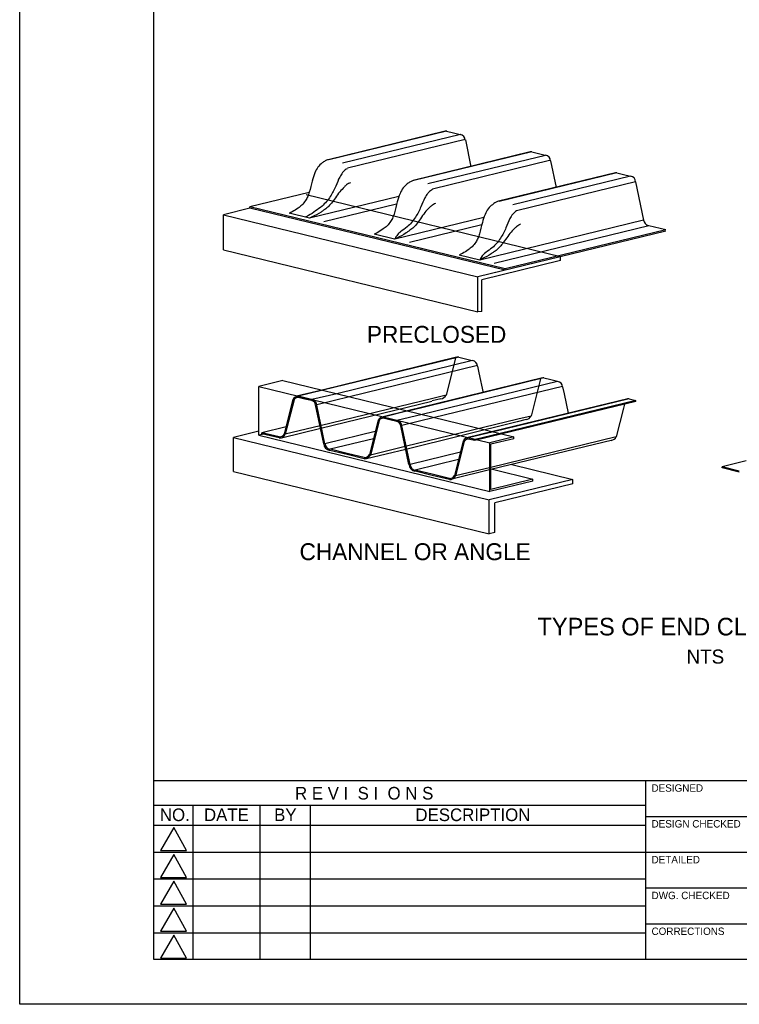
# Model space of a CAD drawing. Extents: x 0 to 34, y 0 to 23.5.
# Drawn here: x 0 to 8.04, y 0 to 11 of the extents above; entities that cross this region are included whole.
import ezdxf

# ---------------------------------------------------------------- set-up
doc = ezdxf.new("R2010")
doc.units = 0
for name, color, linetype in [('BORDER_ANNO_Cutsheet', 7, 'Continuous'), ('BRDG_ANNO_Anno-Sheet', 7, 'Continuous'), ('BRDG_ANNO_General-Notes', 7, 'Continuous'), ('BRDG_BASE_Active-Point', 7, 'Continuous'), ('BRDG_BASE_Hidden-Line', 7, 'Continuous'), ('BRDG_BASE_Obj-Line', 7, 'Continuous')]:
    doc.layers.add(name, color=color, linetype=linetype)

msp = doc.modelspace()

# ---------------------------------------------------------------- linework, layer by layer
at = {"layer": 'BORDER_ANNO_Cutsheet'}
msp.add_lwpolyline([(0, 22), (34, 22), (34, 0), (0, 0)], close=True, dxfattribs=at)
at = {"layer": 'BRDG_ANNO_Anno-Sheet'}
for p, q in [((1.5, 2.5), (19.25, 2.5)), ((7, 0.5), (7, 2.5)), ((1.5, 2.225), (7, 2.225)), ((1.938, 0.5), (1.938, 2.225)), ((2.688, 0.5), (2.688, 2.225)), ((3.25, 0.5), (3.25, 2.219)), ((7, 2.1), (9.5, 2.1)), ((1.498, 2), (7, 2)), ((1.498, 1.7), (7, 1.7)), ((7, 1.7), (9.5, 1.7)), ((1.498, 1.4), (7, 1.4)), ((7, 1.3), (9.5, 1.3)), ((1.498, 1.1), (7, 1.1)), ((7, 0.9), (9.5, 0.9)), ((1.498, 0.8), (7, 0.8))]:
    msp.add_line(p, q, dxfattribs=at)
msp.add_lwpolyline([(1.5, 21.5), (33.5, 21.5), (33.5, 0.5), (1.5, 0.5)], close=True, dxfattribs=at)
for points in [[(1.722, 1.974), (1.574, 1.718), (1.864, 1.718), (1.722, 1.974)], [(1.722, 1.674), (1.574, 1.417), (1.864, 1.417), (1.722, 1.674)], [(1.722, 1.374), (1.574, 1.117), (1.864, 1.117), (1.722, 1.374)], [(1.722, 1.074), (1.574, 0.818), (1.864, 0.818), (1.722, 1.074)], [(1.722, 0.774), (1.574, 0.517), (1.864, 0.517), (1.722, 0.774)]]:
    msp.add_lwpolyline(points, dxfattribs=at)
at = {"layer": 'BRDG_BASE_Active-Point'}
msp.add_line((0, 0), (0, 0), dxfattribs=at)
at = {"layer": 'BRDG_BASE_Hidden-Line'}
for p, q in [((3.201, 9.046), (6.046, 8.353)), ((4.87, 7.22), (4.765, 6.806)), ((5.82, 6.988), (5.717, 6.572)), ((3.381, 6.862), (3.095, 6.793)), ((3.388, 6.86), (3.112, 6.793)), ((3.543, 6.822), (3.264, 6.755)), ((3.054, 6.757), (2.957, 6.374)), ((3.066, 6.753), (2.969, 6.368)), ((3.188, 6.774), (3.112, 6.793)), ((3.188, 6.761), (3.112, 6.78)), ((3.262, 6.756), (3.188, 6.774)), ((3.262, 6.744), (3.188, 6.761)), ((3.686, 6.788), (3.32, 6.699)), ((4.616, 6.768), (3.357, 6.462)), ((4.607, 6.734), (3.365, 6.432)), ((4.707, 6.765), (4.609, 6.741)), ((4.765, 6.806), (4.616, 6.768)), ((6.886, 6.735), (6.886, 6.747)), ((3.399, 6.263), (3.308, 6.696)), ((3.411, 6.263), (3.321, 6.694)), ((4.334, 6.631), (4.047, 6.561)), ((4.342, 6.629), (4.064, 6.561)), ((4.006, 6.525), (3.909, 6.141)), ((4.017, 6.519), (3.921, 6.136)), ((4.138, 6.542), (4.064, 6.561)), ((4.138, 6.529), (4.064, 6.548)), ((4.214, 6.523), (4.138, 6.542)), ((4.214, 6.51), (4.138, 6.529)), ((4.497, 6.59), (4.216, 6.522)), ((4.638, 6.556), (4.27, 6.466)), ((5.567, 6.536), (4.309, 6.23)), ((5.559, 6.509), (4.316, 6.199)), ((5.659, 6.532), (5.559, 6.509)), ((5.717, 6.572), (5.567, 6.536)), ((2.977, 6.452), (2.708, 6.386)), ((2.899, 6.34), (2.708, 6.386)), ((3.365, 6.432), (2.926, 6.325)), ((3.357, 6.462), (2.969, 6.368)), ((3.987, 6.404), (3.411, 6.263)), ((4.351, 6.031), (4.259, 6.463)), ((4.363, 6.031), (4.271, 6.461)), ((5.287, 6.398), (4.998, 6.327)), ((5.295, 6.396), (5.014, 6.327)), ((2.727, 6.37), (2.673, 6.357)), ((2.899, 6.327), (2.708, 6.374)), ((3.953, 6.319), (3.469, 6.201)), ((4.957, 6.293), (4.861, 5.909)), ((4.968, 6.287), (4.871, 5.903)), ((5.09, 6.31), (5.014, 6.327)), ((5.087, 6.298), (5.014, 6.315)), ((5.393, 6.372), (5.087, 6.298)), ((5.09, 6.31), (5.087, 6.298)), ((5.37, 6.378), (5.09, 6.31)), ((3.66, 6.141), (3.468, 6.188)), ((3.66, 6.154), (3.469, 6.201)), ((4.316, 6.199), (3.878, 6.093)), ((4.309, 6.23), (3.921, 6.136)), ((4.926, 6.168), (4.363, 6.031)), ((3.851, 6.108), (3.66, 6.154)), ((3.851, 6.095), (3.66, 6.141)), ((4.905, 6.086), (4.42, 5.968)), ((4.612, 5.922), (4.42, 5.968)), ((4.611, 5.909), (4.42, 5.955)), ((5.267, 5.973), (4.829, 5.866)), ((5.267, 5.999), (4.871, 5.903)), ((4.803, 5.876), (4.612, 5.922)), ((4.803, 5.863), (4.612, 5.909))]:
    msp.add_line(p, q, dxfattribs=at)
for centre, radius, start in [((4.698, 6.84), 0.0756, 277.0721), ((5.65, 6.608), 0.0756, 277.0721), ((2.902, 6.403), 0.063, 268.0538), ((2.902, 6.403), 0.0756, 268.1455), ((3.853, 6.171), 0.063, 268.0538), ((3.853, 6.171), 0.0756, 268.1455), ((4.805, 5.938), 0.063, 268.0538), ((4.805, 5.938), 0.0756, 268.1455)]:
    msp.add_arc(centre, radius, start, 332.3893, dxfattribs=at)
for centre, major_axis, ratio, start_param, end_param in [((4.89, 7.17), (-0.0292, -0.0558), 0.798042, 3.385822, 4.130623), ((5.842, 6.938), (-0.0292, -0.0558), 0.798042, 3.385822, 4.132768), ((3.097, 6.732), (-0.0292, -0.0558), 0.798042, 3.457653, 4.663306), ((3.1, 6.731), (-0.0234, -0.0446), 0.795456, 3.477186, 4.66277), ((3.257, 6.693), (0.0504, 0.0003), 0.98658, 0, 1.427526), ((3.257, 6.693), (0.063, 0.0004), 0.993999, 0, 1.440552), ((4.048, 6.499), (-0.0292, -0.0558), 0.798042, 3.449597, 4.663306), ((4.051, 6.499), (-0.0234, -0.0446), 0.795456, 3.475376, 4.66277), ((4.209, 6.46), (0.0504, 0.0003), 0.98658, 0, 1.427526), ((4.209, 6.46), (0.063, 0.0004), 0.993999, 0, 1.440552), ((5, 6.267), (-0.0295, -0.0564), 0.80021, 3.465294, 4.663306), ((5.003, 6.266), (-0.0234, -0.0446), 0.795456, 3.48851, 4.66277), ((3.486, 6.261), (-0.0865, -0.0005), 0.87395, 0, 1.32709), ((3.484, 6.262), (-0.071, -0.0004), 0.886538, 0, 1.32709), ((4.438, 6.029), (-0.0865, -0.0005), 0.87395, 0, 1.32709), ((4.435, 6.029), (-0.071, -0.0004), 0.886538, 0, 1.32709)]:
    msp.add_ellipse(centre, major_axis=major_axis, ratio=ratio, start_param=start_param, end_param=end_param, dxfattribs=at)
at = {"layer": 'BRDG_BASE_Obj-Line'}
for p, q in [((4.755, 9.755), (3.447, 9.436)), ((4.772, 9.755), (3.454, 9.435)), ((4.927, 9.718), (3.608, 9.397)), ((4.772, 9.755), (4.848, 9.736)), ((4.848, 9.736), (4.923, 9.719)), ((4.98, 9.662), (3.663, 9.341)), ((4.981, 9.656), (5.044, 9.357)), ((5.707, 9.523), (4.398, 9.204)), ((5.724, 9.523), (4.406, 9.202)), ((5.876, 9.484), (4.56, 9.165)), ((5.724, 9.523), (5.799, 9.504)), ((5.799, 9.504), (5.874, 9.486)), ((5.92, 9.426), (4.615, 9.108)), ((5.931, 9.423), (5.995, 9.124)), ((6.659, 9.29), (5.35, 8.972)), ((6.674, 9.29), (5.358, 8.97)), ((6.828, 9.252), (5.512, 8.932)), ((6.674, 9.29), (6.75, 9.272)), ((6.75, 9.272), (6.826, 9.253)), ((6.883, 9.19), (5.566, 8.87)), ((6.883, 9.19), (6.974, 8.761)), ((3.236, 9.069), (2.572, 8.908)), ((4.237, 9.023), (3.241, 8.781)), ((4.213, 8.94), (3.4, 8.742)), ((2.572, 8.893), (2.278, 8.821)), ((2.278, 8.821), (5.122, 8.127)), ((2.278, 8.43), (2.278, 8.821)), ((5.427, 8.215), (2.572, 8.908)), ((2.572, 8.893), (2.572, 8.908)), ((5.427, 8.202), (2.572, 8.893)), ((3.241, 8.781), (3.011, 8.837)), ((5.189, 8.791), (4.192, 8.549)), ((5.165, 8.708), (4.358, 8.511)), ((6.974, 8.761), (5.143, 8.315)), ((7.032, 8.698), (5.303, 8.277)), ((7.222, 8.652), (7.032, 8.698)), ((4.191, 8.549), (3.962, 8.605)), ((7.222, 8.639), (5.122, 8.127)), ((7.222, 8.652), (5.427, 8.215)), ((2.278, 8.43), (5.122, 7.737)), ((5.143, 8.315), (4.913, 8.371)), ((6.055, 8.355), (5.122, 8.127)), ((6.046, 8.308), (5.164, 8.094)), ((6.046, 8.308), (6.046, 8.353)), ((5.427, 8.202), (5.427, 8.215)), ((5.122, 7.737), (5.122, 8.127)), ((5.164, 7.739), (5.164, 8.094)), ((5.164, 7.739), (5.122, 7.737)), ((4.884, 7.228), (3.382, 6.862)), ((4.908, 7.23), (3.389, 6.86)), ((5.062, 7.192), (3.544, 6.822)), ((4.908, 7.23), (4.984, 7.211)), ((4.984, 7.211), (5.059, 7.193)), ((5.116, 7.136), (3.687, 6.788)), ((5.117, 7.13), (5.133, 7.053)), ((5.133, 7.053), (5.179, 6.832)), ((2.942, 6.969), (2.673, 6.903)), ((2.942, 6.969), (5.523, 6.34)), ((5.843, 6.998), (4.335, 6.63)), ((5.859, 6.998), (4.343, 6.628)), ((6.011, 6.959), (4.497, 6.59)), ((5.859, 6.998), (5.935, 6.979)), ((5.935, 6.979), (6.01, 6.96)), ((2.673, 6.903), (5.253, 6.274)), ((2.673, 6.357), (2.673, 6.903)), ((6.066, 6.903), (4.638, 6.556)), ((6.067, 6.898), (6.084, 6.821)), ((6.084, 6.82), (6.13, 6.603)), ((6.796, 6.765), (5.287, 6.398)), ((6.811, 6.764), (5.295, 6.396)), ((6.886, 6.747), (5.37, 6.378)), ((6.886, 6.735), (5.393, 6.372)), ((6.811, 6.764), (6.886, 6.747)), ((6.748, 6.659), (6.667, 6.34)), ((6.759, 6.704), (6.748, 6.659)), ((2.673, 6.403), (2.388, 6.333)), ((2.708, 6.374), (2.708, 6.386)), ((2.388, 6.333), (5.249, 5.637)), ((2.388, 5.953), (2.388, 6.333)), ((2.673, 6.357), (5.253, 5.728)), ((5.523, 6.34), (5.253, 6.274)), ((5.253, 5.728), (5.253, 6.274)), ((6.667, 6.34), (5.267, 5.999)), ((5.523, 6.319), (5.267, 6.256)), ((6.627, 6.304), (5.267, 5.973)), ((5.523, 6.319), (5.523, 6.34)), ((5.267, 5.753), (5.267, 6.256)), ((8.121, 6.071), (7.852, 6.006)), ((2.388, 5.953), (5.249, 5.257)), ((5.286, 5.978), (5.737, 5.868)), ((5.5, 6.03), (6.182, 5.864)), ((8.043, 5.958), (7.852, 6.006)), ((7.852, 5.993), (7.852, 6.006)), ((8.043, 5.946), (7.852, 5.993)), ((6.182, 5.864), (5.249, 5.637)), ((5.737, 5.846), (5.253, 5.728)), ((5.737, 5.868), (5.267, 5.753)), ((5.737, 5.846), (5.737, 5.868)), ((6.182, 5.815), (6.182, 5.864)), ((6.182, 5.815), (5.309, 5.603)), ((5.249, 5.257), (5.249, 5.637)), ((5.309, 5.272), (5.309, 5.603)), ((5.309, 5.272), (5.249, 5.257))]:
    msp.add_line(p, q, dxfattribs=at)
msp.add_arc((6.601, 6.375), 0.0756, 277.0721, 332.3893, dxfattribs=at)
for centre, major_axis, ratio, start_param, end_param in [((4.755, 9.695), (-0.0292, -0.0558), 0.798042, 3.385822, 3.701619), ((4.917, 9.655), (0.063, 0.0004), 0.993999, 0, 1.440552), ((5.706, 9.463), (-0.0292, -0.0558), 0.798042, 3.385822, 3.701619), ((5.869, 9.423), (0.063, 0.0004), 0.993999, 0, 1.440552), ((6.657, 9.23), (-0.0292, -0.0558), 0.798042, 3.385822, 3.701619), ((6.82, 9.19), (0.063, 0.0004), 0.993999, 0, 1.440552), ((7.045, 8.761), (-0.071, -0.0004), 0.886538, 0, 1.32709), ((5.053, 7.13), (0.063, 0.0004), 0.993999, 0, 1.440552), ((6.005, 6.897), (0.063, 0.0004), 0.993999, 0, 1.440552), ((6.793, 6.705), (-0.0292, -0.0558), 0.798042, 3.385822, 3.701619)]:
    msp.add_ellipse(centre, major_axis=major_axis, ratio=ratio, start_param=start_param, end_param=end_param, dxfattribs=at)
for points in [[(3.447, 9.436), (3.415, 9.422), (3.381, 9.399), (3.334, 9.352), (3.3, 9.29), (3.268, 9.197), (3.237, 9.073), (3.22, 9.025), (3.194, 8.979), (3.154, 8.928), (3.111, 8.896), (3.046, 8.853), (3.012, 8.836)], [(3.663, 9.335), (3.638, 9.321), (3.608, 9.291), (3.577, 9.242), (3.533, 9.141), (3.471, 9.026), (3.379, 8.917), (3.308, 8.864), (3.227, 8.811), (3.191, 8.793)], [(3.696, 9.179), (3.654, 9.157), (3.629, 9.132), (3.577, 9.077), (3.528, 9.01), (3.484, 8.95), (3.443, 8.906), (3.397, 8.871), (3.369, 8.851), (3.263, 8.794), (3.241, 8.781)], [(4.398, 9.204), (4.367, 9.19), (4.332, 9.166), (4.285, 9.12), (4.251, 9.057), (4.22, 8.965), (4.189, 8.841), (4.171, 8.792), (4.145, 8.746), (4.106, 8.696), (4.063, 8.664), (3.997, 8.62), (3.963, 8.604)], [(4.615, 9.103), (4.59, 9.089), (4.56, 9.058), (4.528, 9.01), (4.484, 8.909), (4.423, 8.793), (4.33, 8.684), (4.258, 8.631), (4.222, 8.597), (4.192, 8.549)], [(4.647, 8.947), (4.606, 8.923), (4.579, 8.9), (4.528, 8.845), (4.48, 8.777), (4.436, 8.717), (4.394, 8.672), (4.349, 8.639), (4.319, 8.618), (4.215, 8.56), (4.191, 8.549)], [(5.35, 8.972), (5.318, 8.958), (5.284, 8.933), (5.237, 8.888), (5.202, 8.825), (5.171, 8.733), (5.139, 8.608), (5.122, 8.559), (5.097, 8.514), (5.056, 8.464), (5.014, 8.43), (4.948, 8.388), (4.915, 8.371)], [(5.566, 8.87), (5.541, 8.856), (5.511, 8.826), (5.48, 8.778), (5.435, 8.675), (5.374, 8.56), (5.281, 8.452), (5.21, 8.399), (5.157, 8.345), (5.143, 8.315)], [(5.598, 8.715), (5.557, 8.691), (5.531, 8.668), (5.48, 8.611), (5.431, 8.545), (5.387, 8.485), (5.346, 8.44), (5.301, 8.406), (5.271, 8.385), (5.167, 8.328), (5.143, 8.315)]]:
    msp.add_spline(points, degree=3, dxfattribs=at)

# ---------------------------------------------------------------- texts
at = {"layer": 'BRDG_ANNO_Anno-Sheet'}
for s, height, p in [('R E V I  S I  O N S', 0.14062, (3.077, 2.288)), ('DESIGNED', 0.0825, (7.062, 2.375)), ('NO.', 0.1406, (1.567, 2.047)), ('DATE', 0.1406, (2.06, 2.047)), ('BY', 0.1406, (2.844, 2.047)), ('DESCRIPTION', 0.14062, (4.423, 2.047)), ('DESIGN CHECKED', 0.08281, (7.062, 1.975)), ('DETAILED', 0.0828, (7.062, 1.575)), ('DWG. CHECKED', 0.08281, (7.062, 1.175)), ('CORRECTIONS', 0.0825, (7.062, 0.775))]:
    msp.add_text(s, height=height, dxfattribs=at).set_placement(p)
at = {"layer": 'BRDG_ANNO_General-Notes'}
for s, height, p in [('PRECLOSED', 0.1889, (3.881, 7.39)), ('CHANNEL OR ANGLE', 0.18894, (3.128, 4.962)), ('TYPES OF END CLOSURES', 0.19681, (5.788, 4.121)), ('NTS', 0.1575, (7.453, 3.806))]:
    msp.add_text(s, height=height, dxfattribs=at).set_placement(p)

doc.saveas('drawing.dxf')
